(* Logix 5000 project; controller Motion_Axis_AOIs_AMCI_RSLogix_V31 vendor 1 type 14 code 108 rev 31.11; software revision 31.02; part 4 of 7 *)

ADD_ON_INSTRUCTION AMCI_MA_SV_Linear_Follower   (* revision 1.1, vendor AMCI, ExecuteEnableInFalse *)
// Only for SVXXXE2 motion devices.
// Revision note:
// Version 1.1:  Corrected mistake in the text on the Help Tab.
// Help:
// MOTION AXIS SV CIRCULAR FOLLOWER
// These AOIs will only work with the SV motion devices.  The SMD and SD  motion devices have their own follower AOIs.
// AXIS INPUT DATA:  Input data from AMCI motion device.   Uses the AMCI_Motion_Axis_Input_Data User Defined Data Type.
// AXIS OUTPUT DATA; Output data from the AOI to the AMCI motion device.   Uses the AMCI_Motion_Axis_Output_Data User Defined Data Type.
// FOLLOWER POSITION: REAL DATA TYPE position directly from the motion axis.
// FOLLOWER VELOCITY: REAL DATA TYPE velocity directly from the motion axis.
// FOLLOWER ACCELERATION: REAL DATA TYPE acceleration directly from the motion axis.
// RAMP ACCELERATION: An actual value or INT value used to transition from no motion to motion.   Once
//                                          motion is occurring, the follower acceleration will be used.  Range of 0 to 15,999.
// DECELERATION: An actual value or INT value used to transition from motion to no motion.   Range of 0 to
//                              15,999.
// EN (Enable) Set when rung is true, Reset when rung is false
// DN (Done) Set when command is sent to the motion device.  Reset when the rung is false.
// ER (Error) Set when a command or input error failed to clear.  Reset when the rung is false.
// IP (In Process) Set when motion is occurring.   Reset when the rung goes false.
VAR_IN_OUT
   Axis_Input_Data : AMCI_Motion_Axis_Input_Data; {required}
   Axis_Output_Data : AMCI_Motion_Axis_Output_Data; {required}
END_VAR
VAR_INPUT
   Follower_Position : REAL; {required}
   Follower_Velocity : REAL; {required}
   Follower_Acceleration : REAL; {required}
   Ramp_Acceleration : INT; {required}
   Deceleration : INT; {required}
   Maximum_Move_Torque : INT;
END_VAR
VAR_OUTPUT
   EN : BOOL; {visible}
   ER : BOOL; {visible}
   DN : BOOL; {access Read Only, visible}
   IP : BOOL; {access Read Only, visible}
END_VAR
VAR
   command_data_block : INT[10];
        [2]   // Upper Target Position
        [4]   // Upper Programmed Speed
        [1]   // Command Bits LSW
        [3]   // Lower Target Position
        [5]   // Lower Programmed Speed
        [0]   // Command Bits MSW
   axis_follower_position : DINT;
   axis_follower_velocity : DINT;
END_VAR

ROUTINE EnableInFalse   (* ladder *)
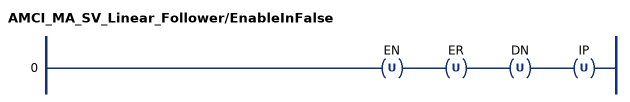
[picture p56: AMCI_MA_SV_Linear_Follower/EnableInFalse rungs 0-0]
   0: OTU(EN)OTU(ER)OTU(DN)OTU(IP);
END_ROUTINE

ROUTINE Logic   (* ladder *)
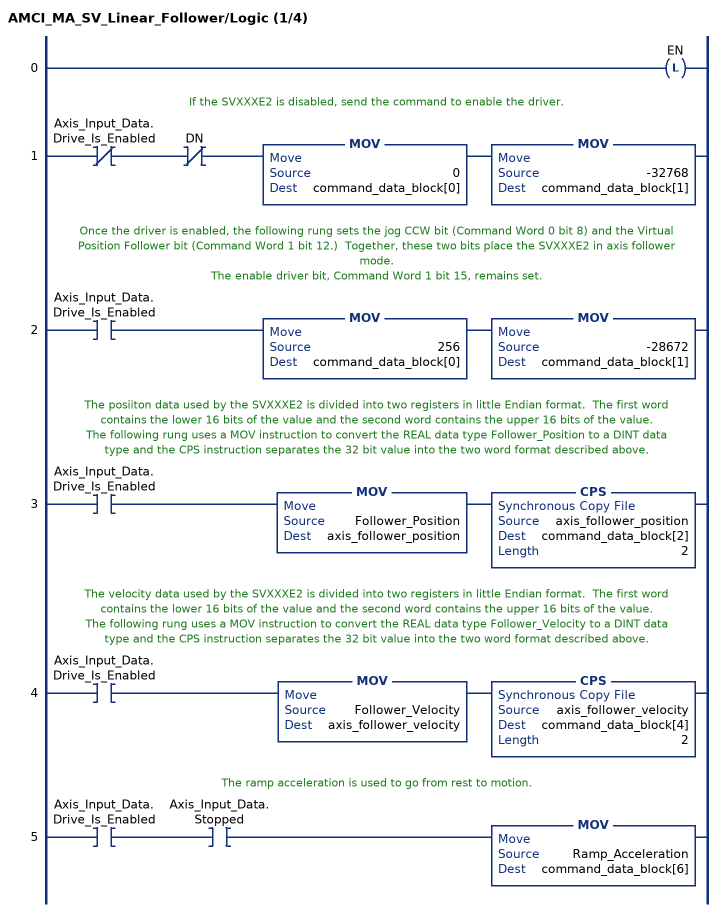
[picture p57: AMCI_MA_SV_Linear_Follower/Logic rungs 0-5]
   0: OTL(EN);
   // If the SVXXXE2 is disabled, send the command to enable the driver.
   1: XIO(Axis_Input_Data.Drive_Is_Enabled)XIO(DN)MOV(0,command_data_block[0])MOV(-32768,command_data_block[1]);
   // Once the driver is enabled, the following rung sets the jog CCW bit (Command Word 0 bit 8) and the Virtual Position Follower bit (Command Word 1 bit 12.)  Together, these two bits place the SVXXXE2 in axis follower mode.
   // The enable driver bit, Command Word 1 bit 15, remains set.
   2: XIC(Axis_Input_Data.Drive_Is_Enabled)MOV(256,command_data_block[0])MOV(-28672,command_data_block[1]);
   // The posiiton data used by the SVXXXE2 is divided into two registers in little Endian format.  The first word contains the lower 16 bits of the value and the second word contains the upper 16 bits of the value.
   // The following rung uses a MOV instruction to convert the REAL data type Follower_Position to a DINT data type and the CPS instruction separates the 32 bit value into the two word format described above.
   3: XIC(Axis_Input_Data.Drive_Is_Enabled)MOV(Follower_Position,axis_follower_position)CPS(axis_follower_position,command_data_block[2],2);
   // The velocity data used by the SVXXXE2 is divided into two registers in little Endian format.  The first word contains the lower 16 bits of the value and the second word contains the upper 16 bits of the value.
   // The following rung uses a MOV instruction to convert the REAL data type Follower_Velocity to a DINT data type and the CPS instruction separates the 32 bit value into the two word format described above.
   4: XIC(Axis_Input_Data.Drive_Is_Enabled)MOV(Follower_Velocity,axis_follower_velocity)CPS(axis_follower_velocity,command_data_block[4],2);
   // The ramp acceleration is used to go from rest to motion.
   5: XIC(Axis_Input_Data.Drive_Is_Enabled)XIC(Axis_Input_Data.Stopped)MOV(Ramp_Acceleration,command_data_block[6]);
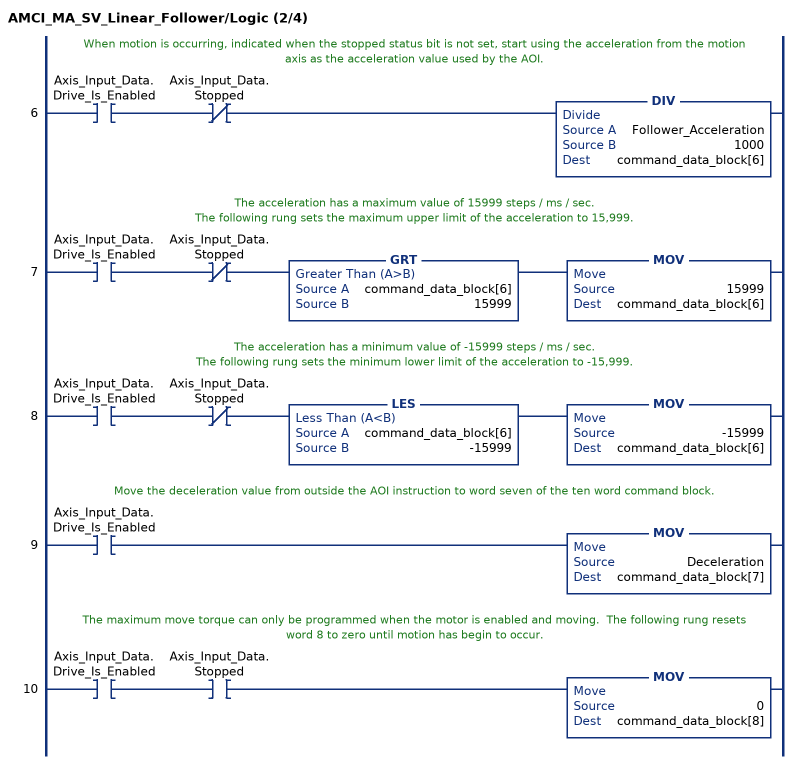
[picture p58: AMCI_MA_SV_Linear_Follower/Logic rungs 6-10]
   // When motion is occurring, indicated when the stopped status bit is not set, start using the acceleration from the motion axis as the acceleration value used by the AOI.
   6: XIC(Axis_Input_Data.Drive_Is_Enabled)XIO(Axis_Input_Data.Stopped)DIV(Follower_Acceleration,1000,command_data_block[6]);
   // The acceleration has a maximum value of 15999 steps / ms / sec.
   // The following rung sets the maximum upper limit of the acceleration to 15,999.
   7: XIC(Axis_Input_Data.Drive_Is_Enabled)XIO(Axis_Input_Data.Stopped)GRT(command_data_block[6],15999)MOV(15999,command_data_block[6]);
   // The acceleration has a minimum value of -15999 steps / ms / sec.
   // The following rung sets the minimum lower limit of the acceleration to -15,999.
   8: XIC(Axis_Input_Data.Drive_Is_Enabled)XIO(Axis_Input_Data.Stopped)LES(command_data_block[6],-15999)MOV(-15999,command_data_block[6]);
   // Move the deceleration value from outside the AOI instruction to word seven of the ten word command block.
   9: XIC(Axis_Input_Data.Drive_Is_Enabled)MOV(Deceleration,command_data_block[7]);
   // The maximum move torque can only be programmed when the motor is enabled and moving.  The following rung resets word 8 to zero until motion has begin to occur.
   10: XIC(Axis_Input_Data.Drive_Is_Enabled)XIC(Axis_Input_Data.Stopped)MOV(0,command_data_block[8]);
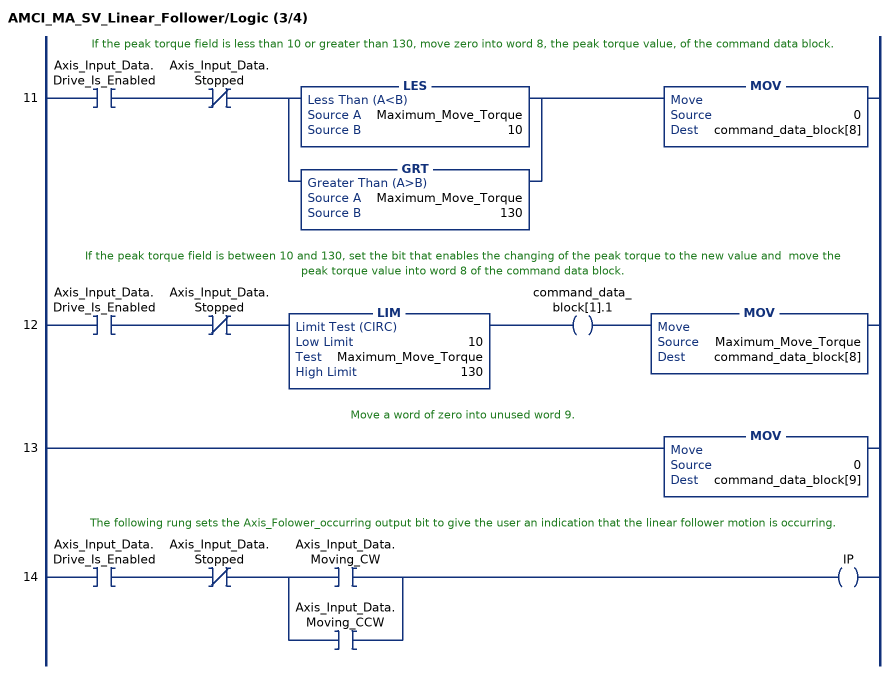
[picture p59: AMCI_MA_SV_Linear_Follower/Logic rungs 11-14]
   // If the peak torque field is less than 10 or greater than 130, move zero into word 8, the peak torque value, of the command data block.
   11: XIC(Axis_Input_Data.Drive_Is_Enabled)XIO(Axis_Input_Data.Stopped)[LES(Maximum_Move_Torque,10) ,GRT(Maximum_Move_Torque,130) ]MOV(0,command_data_block[8]);
   // If the peak torque field is between 10 and 130, set the bit that enables the changing of the peak torque to the new value and  move the peak torque value into word 8 of the command data block.
   12: XIC(Axis_Input_Data.Drive_Is_Enabled)XIO(Axis_Input_Data.Stopped)LIM(10,Maximum_Move_Torque,130)OTE(command_data_block[1].1)MOV(Maximum_Move_Torque,command_data_block[8]);
   // Move a word of zero into unused word 9.
   13: MOV(0,command_data_block[9]);
   // The following rung sets the Axis_Folower_occurring output bit to give the user an indication that the linear follower motion is occurring.
   14: XIC(Axis_Input_Data.Drive_Is_Enabled)XIO(Axis_Input_Data.Stopped)[XIC(Axis_Input_Data.Moving_CW) ,XIC(Axis_Input_Data.Moving_CCW) ]OTE(IP);
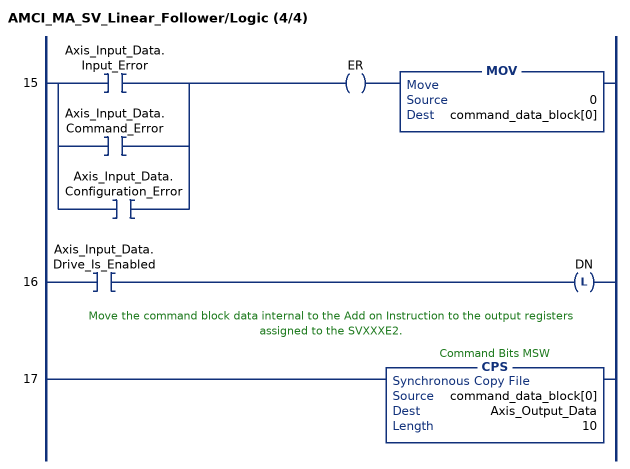
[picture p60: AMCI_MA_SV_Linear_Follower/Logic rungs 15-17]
   15: [XIC(Axis_Input_Data.Input_Error) ,XIC(Axis_Input_Data.Command_Error) ,XIC(Axis_Input_Data.Configuration_Error) ]OTE(ER)MOV(0,command_data_block[0]);
   16: XIC(Axis_Input_Data.Drive_Is_Enabled)OTL(DN);
   // Move the command block data internal to the Add on Instruction to the output registers assigned to the SVXXXE2.
   17: CPS(command_data_block[0],Axis_Output_Data,10);
END_ROUTINE
END_ADD_ON_INSTRUCTION

ADD_ON_INSTRUCTION AMCI_MA_SV_Linear_Follower_CIPSync   (* revision 1.0, vendor AMCI, ExecuteEnableInFalse *)
// Only for SVXXXE2 motion devices.
// Revision note:
// 8/8/24.  Added CIPSync functionality to a previously existing AOI.  The abiltiy to change the maximum move torque is no longer available because the time value uses the same output words as the torque value.
// Help:
// MOTION AXIS SV CIRCULAR FOLLOWER
// These AOIs will only work with the SD and SMD motion devices.  The SV motion devices have their own follower AOIs.
// AXIS INPUT DATA:  Input data from AMCI motion device.   Uses the AMCI_Motion_Axis_Input_Data User Defined Data Type.
// AXIS OUTPUT DATA; Output data from the AOI to the AMCI motion device.   Uses the AMCI_Motion_Axis_Output_Data User Defined Data Type.
// FOLLOWER POSITION: REAL DATA TYPE position directly from the motion axis.
// FOLLOWER VELOCITY: REAL DATA TYPE velocity directly from the motion axis.
// FOLLOWER ACCELERATION: REAL DATA TYPE acceleration directly from the motion axis.
// RAMP ACCELERATION: An actual value or INT value used to transition from no motion to motion.   Once
//                                          motion is occurring, the follower acceleration will be used.  Range of 0 to 15,999.
// DECELERATION: An actual value or INT value used to transition from motion to no motion.   Range of 0 to
//                              15,999.
// EN (Enable) Set when rung is true, Reset when rung is false
// DN (Done) Set when command is sent to the motion device.  Reset when the rung is false.
// ER (Error) Set when a command or input error failed to clear.  Reset when the rung is false.
// IP (In Process) Set when motion is occurring.   Reset when the rung goes false.
VAR_IN_OUT
   Axis_Input_Data : AMCI_Motion_Axis_Input_Data; {required}
   Axis_Output_Data : AMCI_Motion_Axis_Output_Data; {required}
END_VAR
VAR_INPUT
   current_system_time : DINT; {required}
   Follower_Position : REAL; {required}
   Follower_Velocity : REAL; {required}
   Follower_Acceleration : REAL; {required}
   Ramp_Acceleration : INT; {required}
   Deceleration : INT; {required}
END_VAR
VAR_OUTPUT
   EN : BOOL; {visible}
   ER : BOOL; {visible}
   DN : BOOL; {access Read Only, visible}
   IP : BOOL; {access Read Only, visible}
END_VAR
VAR
   command_data_block : INT[10];
        [2]   // Upper Target Position
        [4]   // Upper Programmed Speed
        [5]   // Lower Programmed Speed
        [0]   // Command Bits MSW
        [1]   // Command Bits LSW
        [3]   // Lower Target Position
   axis_follower_position : DINT;
   axis_follower_velocity : DINT;
END_VAR

ROUTINE EnableInFalse   (* ladder *)
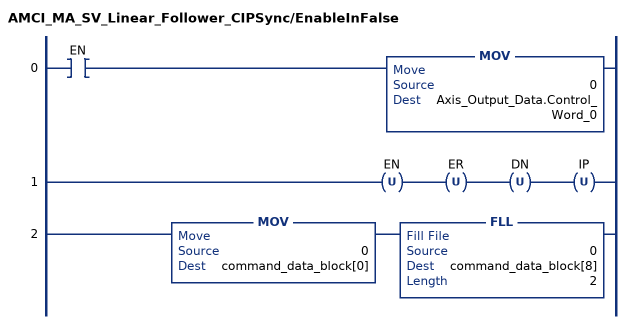
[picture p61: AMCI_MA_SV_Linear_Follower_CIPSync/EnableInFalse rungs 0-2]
   0: XIC(EN)MOV(0,Axis_Output_Data.Control_Word_0);
   1: OTU(EN)OTU(ER)OTU(DN)OTU(IP);
   2: MOV(0,command_data_block[0])FLL(0,command_data_block[8],2);
END_ROUTINE

ROUTINE Logic   (* ladder *)
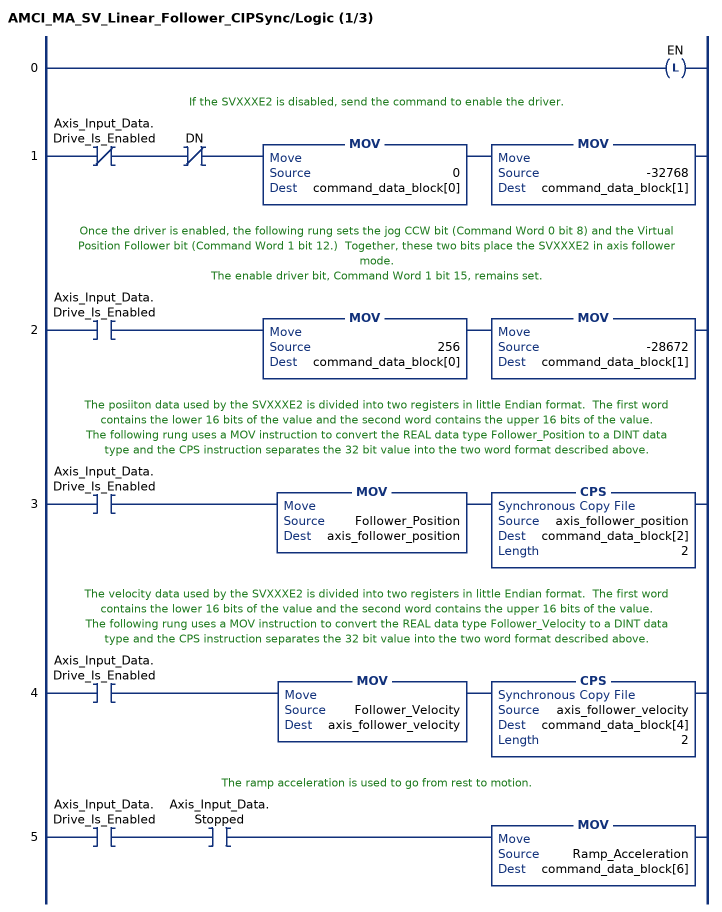
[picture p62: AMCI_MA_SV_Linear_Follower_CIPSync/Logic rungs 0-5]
   0: OTL(EN);
   // If the SVXXXE2 is disabled, send the command to enable the driver.
   1: XIO(Axis_Input_Data.Drive_Is_Enabled)XIO(DN)MOV(0,command_data_block[0])MOV(-32768,command_data_block[1]);
   // Once the driver is enabled, the following rung sets the jog CCW bit (Command Word 0 bit 8) and the Virtual Position Follower bit (Command Word 1 bit 12.)  Together, these two bits place the SVXXXE2 in axis follower mode.
   // The enable driver bit, Command Word 1 bit 15, remains set.
   2: XIC(Axis_Input_Data.Drive_Is_Enabled)MOV(256,command_data_block[0])MOV(-28672,command_data_block[1]);
   // The posiiton data used by the SVXXXE2 is divided into two registers in little Endian format.  The first word contains the lower 16 bits of the value and the second word contains the upper 16 bits of the value.
   // The following rung uses a MOV instruction to convert the REAL data type Follower_Position to a DINT data type and the CPS instruction separates the 32 bit value into the two word format described above.
   3: XIC(Axis_Input_Data.Drive_Is_Enabled)MOV(Follower_Position,axis_follower_position)CPS(axis_follower_position,command_data_block[2],2);
   // The velocity data used by the SVXXXE2 is divided into two registers in little Endian format.  The first word contains the lower 16 bits of the value and the second word contains the upper 16 bits of the value.
   // The following rung uses a MOV instruction to convert the REAL data type Follower_Velocity to a DINT data type and the CPS instruction separates the 32 bit value into the two word format described above.
   4: XIC(Axis_Input_Data.Drive_Is_Enabled)MOV(Follower_Velocity,axis_follower_velocity)CPS(axis_follower_velocity,command_data_block[4],2);
   // The ramp acceleration is used to go from rest to motion.
   5: XIC(Axis_Input_Data.Drive_Is_Enabled)XIC(Axis_Input_Data.Stopped)MOV(Ramp_Acceleration,command_data_block[6]);
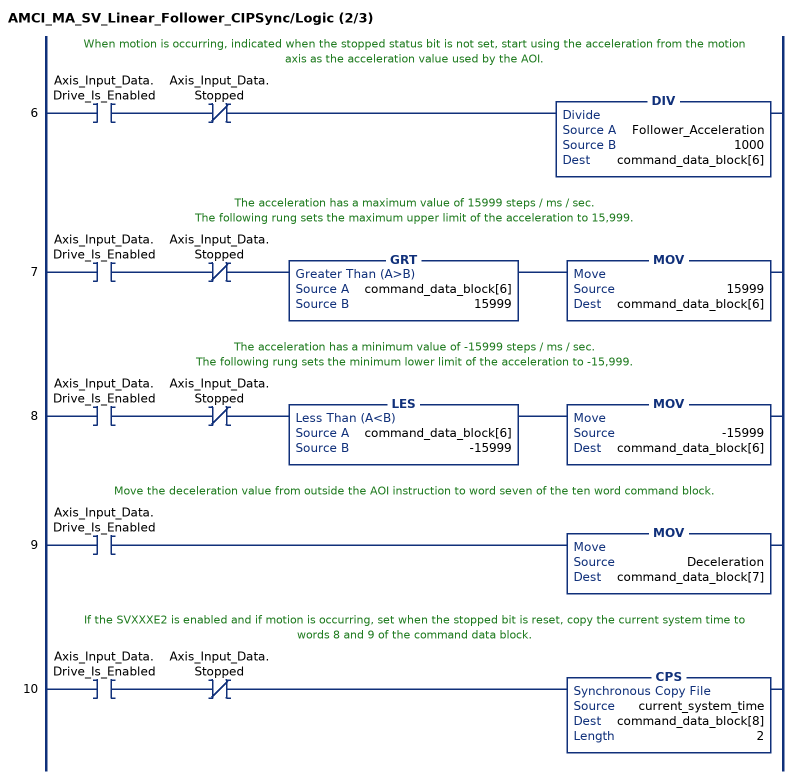
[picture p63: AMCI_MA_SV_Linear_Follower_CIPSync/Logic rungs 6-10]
   // When motion is occurring, indicated when the stopped status bit is not set, start using the acceleration from the motion axis as the acceleration value used by the AOI.
   6: XIC(Axis_Input_Data.Drive_Is_Enabled)XIO(Axis_Input_Data.Stopped)DIV(Follower_Acceleration,1000,command_data_block[6]);
   // The acceleration has a maximum value of 15999 steps / ms / sec.
   // The following rung sets the maximum upper limit of the acceleration to 15,999.
   7: XIC(Axis_Input_Data.Drive_Is_Enabled)XIO(Axis_Input_Data.Stopped)GRT(command_data_block[6],15999)MOV(15999,command_data_block[6]);
   // The acceleration has a minimum value of -15999 steps / ms / sec.
   // The following rung sets the minimum lower limit of the acceleration to -15,999.
   8: XIC(Axis_Input_Data.Drive_Is_Enabled)XIO(Axis_Input_Data.Stopped)LES(command_data_block[6],-15999)MOV(-15999,command_data_block[6]);
   // Move the deceleration value from outside the AOI instruction to word seven of the ten word command block.
   9: XIC(Axis_Input_Data.Drive_Is_Enabled)MOV(Deceleration,command_data_block[7]);
   // If the SVXXXE2 is enabled and if motion is occurring, set when the stopped bit is reset, copy the current system time to words 8 and 9 of the command data block.
   10: XIC(Axis_Input_Data.Drive_Is_Enabled)XIO(Axis_Input_Data.Stopped)CPS(current_system_time,command_data_block[8],2);
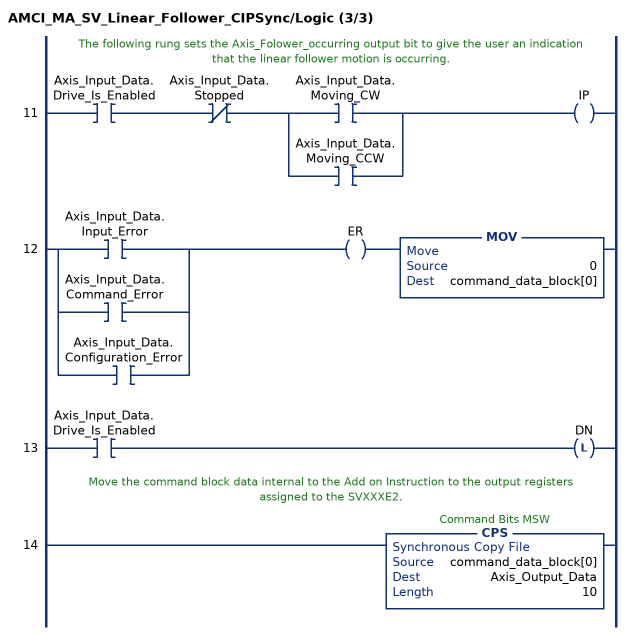
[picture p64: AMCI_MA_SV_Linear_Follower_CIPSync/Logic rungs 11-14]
   // The following rung sets the Axis_Folower_occurring output bit to give the user an indication that the linear follower motion is occurring.
   11: XIC(Axis_Input_Data.Drive_Is_Enabled)XIO(Axis_Input_Data.Stopped)[XIC(Axis_Input_Data.Moving_CW) ,XIC(Axis_Input_Data.Moving_CCW) ]OTE(IP);
   12: [XIC(Axis_Input_Data.Input_Error) ,XIC(Axis_Input_Data.Command_Error) ,XIC(Axis_Input_Data.Configuration_Error) ]OTE(ER)MOV(0,command_data_block[0]);
   13: XIC(Axis_Input_Data.Drive_Is_Enabled)OTL(DN);
   // Move the command block data internal to the Add on Instruction to the output registers assigned to the SVXXXE2.
   14: CPS(command_data_block[0],Axis_Output_Data,10);
END_ROUTINE
END_ADD_ON_INSTRUCTION

ADD_ON_INSTRUCTION AMCI_MAFR   (* revision 1.1, vendor AMCI, ExecuteEnableInFalse *)
// AMCI Reset Errors
// Revision note:
// V1.1 11/17/23 Reset output word 0 to 0 when the rung goes false.
// Help:
// MOTION AXIS FAULT RESET:   Resets Command, Input, and Stall Detect Errors.  It will also reset the Move Complete Status Bit.
// Note: This instruction will maintain the motion device’s current enabled state.  That is, if the device is enabled,
//            it will remain enabled.  If it is disabled, it will remain disabled.
// AXIS INPUT DATA:  Input data from AMCI motion device.   Uses the AMCI_Motion_Axis_Input_Data User Defined Data Type.
// AXIS OUTPUT DATA; Output data from the AOI to the AMCI motion device.   Uses the AMCI_Motion_Axis_Output_Data User Defined Data Type.
// EN (Enable) Set when rung is true, Reset when rung is false
// DN (Done) Set when command is sent to the motion device.  Reset when the rung is false.
// ER (Error) Set when a command or input error failed to clear.  Reset when the rung is false.
VAR_IN_OUT
   Axis_Input_Data : AMCI_Motion_Axis_Input_Data; {required}
   Axis_Output_Data : AMCI_Motion_Axis_Output_Data; {required}
END_VAR
VAR_OUTPUT
   EN : BOOL; {visible}   // set when rung with AOI is true
   DN : BOOL; {access Read Only, visible}   // set when reset error command sent to motion axis
   ER : BOOL; {access Read Only, visible}   // set when reset error command did not clear the error
END_VAR
VAR
   command_data_block : INT[10];
        [3]   // Lower Target Position
        [5]   // Lower Programmed Speed
        [1]   // Command Bits LSW
        [0]   // Command Bits MSW
        [2]   // Upper Target Position
        [4]   // Upper Programmed Speed
END_VAR

ROUTINE EnableInFalse   (* ladder *)
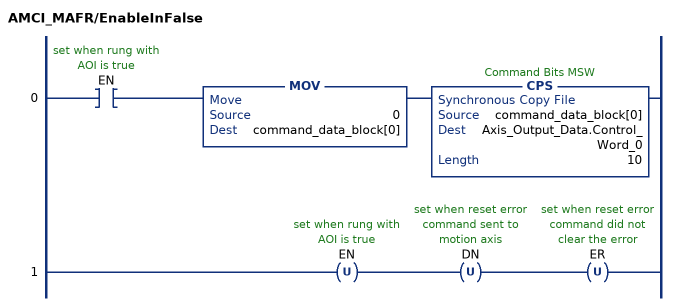
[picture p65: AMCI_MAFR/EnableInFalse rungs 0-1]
   0: XIC(EN)MOV(0,command_data_block[0])CPS(command_data_block[0],Axis_Output_Data.Control_Word_0,10);
   1: OTU(EN)OTU(DN)OTU(ER);
END_ROUTINE

ROUTINE Logic   (* ladder *)
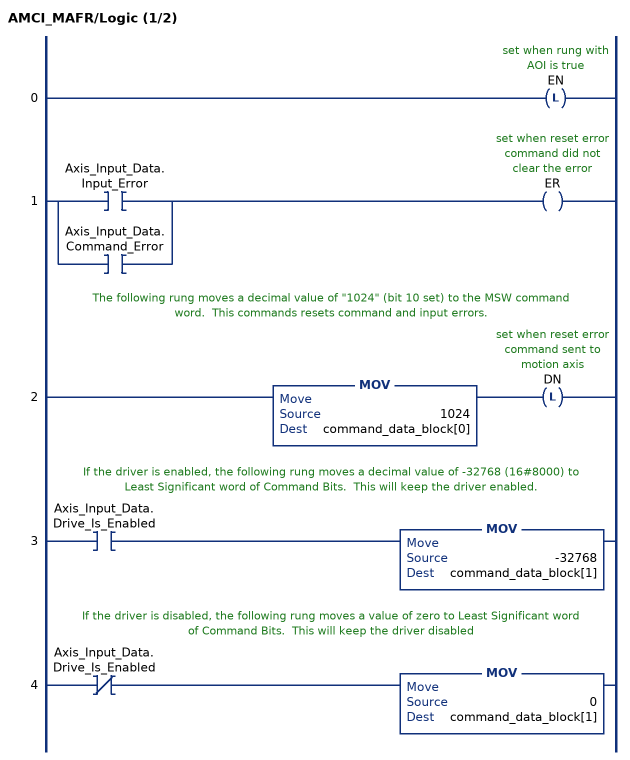
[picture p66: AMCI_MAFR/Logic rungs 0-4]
   0: OTL(EN);
   1: [XIC(Axis_Input_Data.Input_Error) ,XIC(Axis_Input_Data.Command_Error) ]OTE(ER);
   // The following rung moves a decimal value of "1024" (bit 10 set) to the MSW command word.  This commands resets command and input errors.
   2: MOV(1024,command_data_block[0])OTL(DN);
   // If the driver is enabled, the following rung moves a decimal value of -32768 (16#8000) to Least Significant word of Command Bits.  This will keep the driver enabled.
   3: XIC(Axis_Input_Data.Drive_Is_Enabled)MOV(-32768,command_data_block[1]);
   // If the driver is disabled, the following rung moves a value of zero to Least Significant word of Command Bits.  This will keep the driver disabled
   4: XIO(Axis_Input_Data.Drive_Is_Enabled)MOV(0,command_data_block[1]);
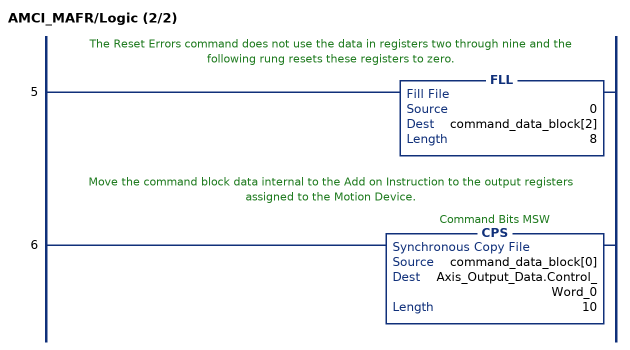
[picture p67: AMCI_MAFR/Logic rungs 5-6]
   // The Reset Errors command does not use the data in registers two through nine and the following rung resets these registers to zero.
   5: FLL(0,command_data_block[2],8);
   // Move the command block data internal to the Add on Instruction to the output registers assigned to the Motion Device.
   6: CPS(command_data_block[0],Axis_Output_Data.Control_Word_0,10);
END_ROUTINE
END_ADD_ON_INSTRUCTION

ADD_ON_INSTRUCTION AMCI_MAH   (* revision 1.0, vendor AMCI, ExecuteEnableInFalse *)
// AMCI Motion Axis Home
// Revision note:
// 11/28/22 Initial release of AOI
// Help:
// MOTION AXIS HOME:   Performs CW or CCW Home Moves to a Home Input.
// AXIS INPUT DATA:  Input data from AMCI motion device.   Uses the AMCI_Motion_Axis_Input_Data User Defined Data Type.
// AXIS OUTPUT DATA; Output data from the AOI to the AMCI motion device.   Uses the AMCI_Motion_Axis_Output_Data User Defined Data Type.
// DIRECTION: 0 = CW Home, 1 = CCW Home
// PROGRAMMED SPEED: Speed of move in units of steps / sec
// ACCELERATION: Acceleration Rate in units of steps / sec / ms
// DECELERATION:  Deceleration Rate in units of steps / sec / ms
// EN (Enable) Set when rung is true, Reset when rung is false
// DN (Done) Set when command is sent to the motion device.  Reset when the rung is false.
// ER (Error) Set when a command or input error failed to clear.  Reset when the rung is false.
// IP (In Process) Set when motion is occurring.   Reset when motion stops or the rung goes false.
// PC (Process Complete) Set when the At Home Status bit is set.   Reset the next time the rung with the AOI                                      goes from false to true.
VAR_IN_OUT
   Axis_Input_Data : AMCI_Motion_Axis_Input_Data; {required}
   Axis_Output_Data : AMCI_Motion_Axis_Output_Data; {required}
END_VAR
VAR_INPUT
   Direction_0_CW_1_CCW : BOOL; {required}   // 0=home CW 1=home CCW
   Programmed_Speed : DINT; {required}
   Acceleration : INT; {required}
   Deceleration : INT; {required}
END_VAR
VAR_OUTPUT
   EN : BOOL; {visible}   // set when rung with AOI is true
   DN : BOOL; {access Read Only, visible}   // set when move was succesfully initiated
   ER : BOOL; {visible}   // input, command, or configuration error
   IP : BOOL; {visible}   // set when motion occurring
   PC : BOOL; {visible}   // set when process complete
END_VAR
VAR
   command_data_block : INT[10];
        [5]   // Lower Programmed Speed
        [0]   // Command Bits MSW
        [2]   // Upper Target Position
        [4]   // Upper Programmed Speed
        [1]   // Command Bits LSW
        [3]   // Lower Target Position
   motion_occurring : BOOL; {access None}
   Internal_Enable : BOOL; {access None}   // set when driver ready to receive motion command
END_VAR

ROUTINE EnableInFalse   (* ladder *)
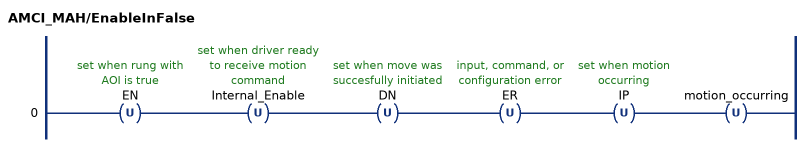
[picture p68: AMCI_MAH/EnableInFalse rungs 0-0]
   0: OTU(EN)OTU(Internal_Enable)OTU(DN)OTU(ER)OTU(IP)OTU(motion_occurring);
END_ROUTINE

ROUTINE Logic   (* ladder *)
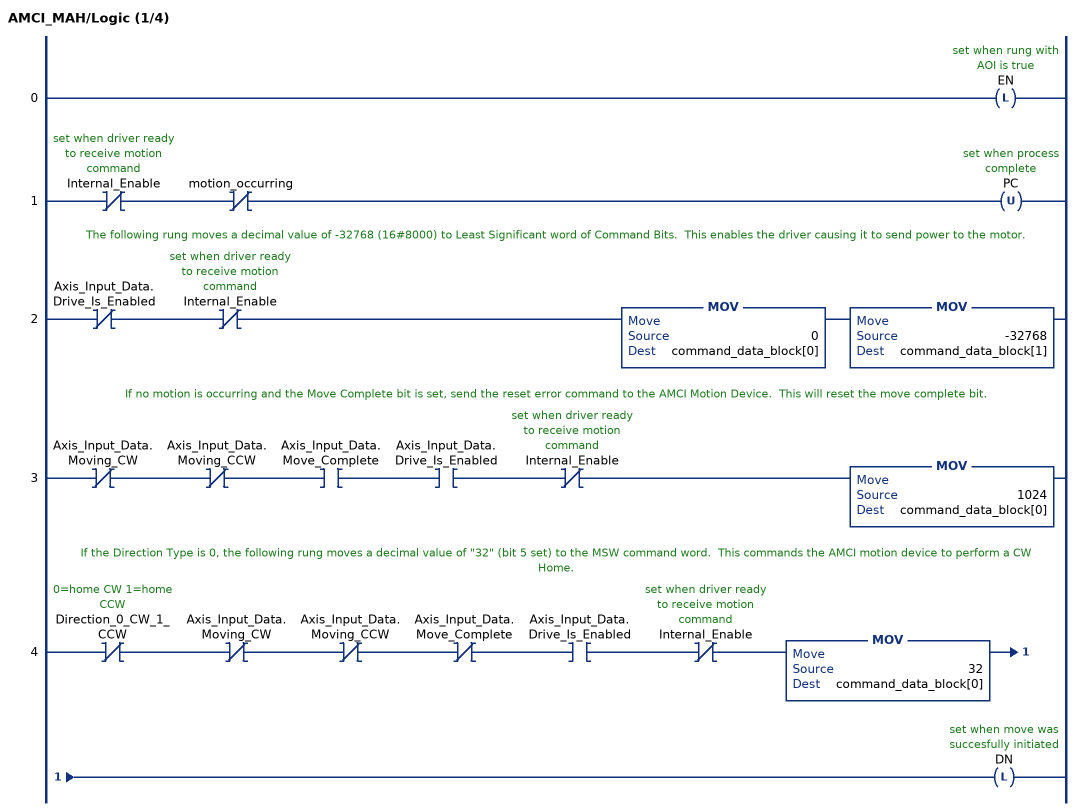
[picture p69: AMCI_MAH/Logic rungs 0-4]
   0: OTL(EN);
   1: XIO(Internal_Enable)XIO(motion_occurring)OTU(PC);
   // The following rung moves a decimal value of -32768 (16#8000) to Least Significant word of Command Bits.  This enables the driver causing it to send power to the motor.
   2: XIO(Axis_Input_Data.Drive_Is_Enabled)XIO(Internal_Enable)MOV(0,command_data_block[0])MOV(-32768,command_data_block[1]);
   // If no motion is occurring and the Move Complete bit is set, send the reset error command to the AMCI Motion Device.  This will reset the move complete bit.
   3: XIO(Axis_Input_Data.Moving_CW)XIO(Axis_Input_Data.Moving_CCW)XIC(Axis_Input_Data.Move_Complete)XIC(Axis_Input_Data.Drive_Is_Enabled)XIO(Internal_Enable)MOV(1024,command_data_block[0]);
   // If the Direction Type is 0, the following rung moves a decimal value of "32" (bit 5 set) to the MSW command word.  This commands the AMCI motion device to perform a CW Home.
   4: XIO(Direction_0_CW_1_CCW)XIO(Axis_Input_Data.Moving_CW)XIO(Axis_Input_Data.Moving_CCW)XIO(Axis_Input_Data.Move_Complete)XIC(Axis_Input_Data.Drive_Is_Enabled)XIO(Internal_Enable)MOV(32,command_data_block[0])OTL(DN);
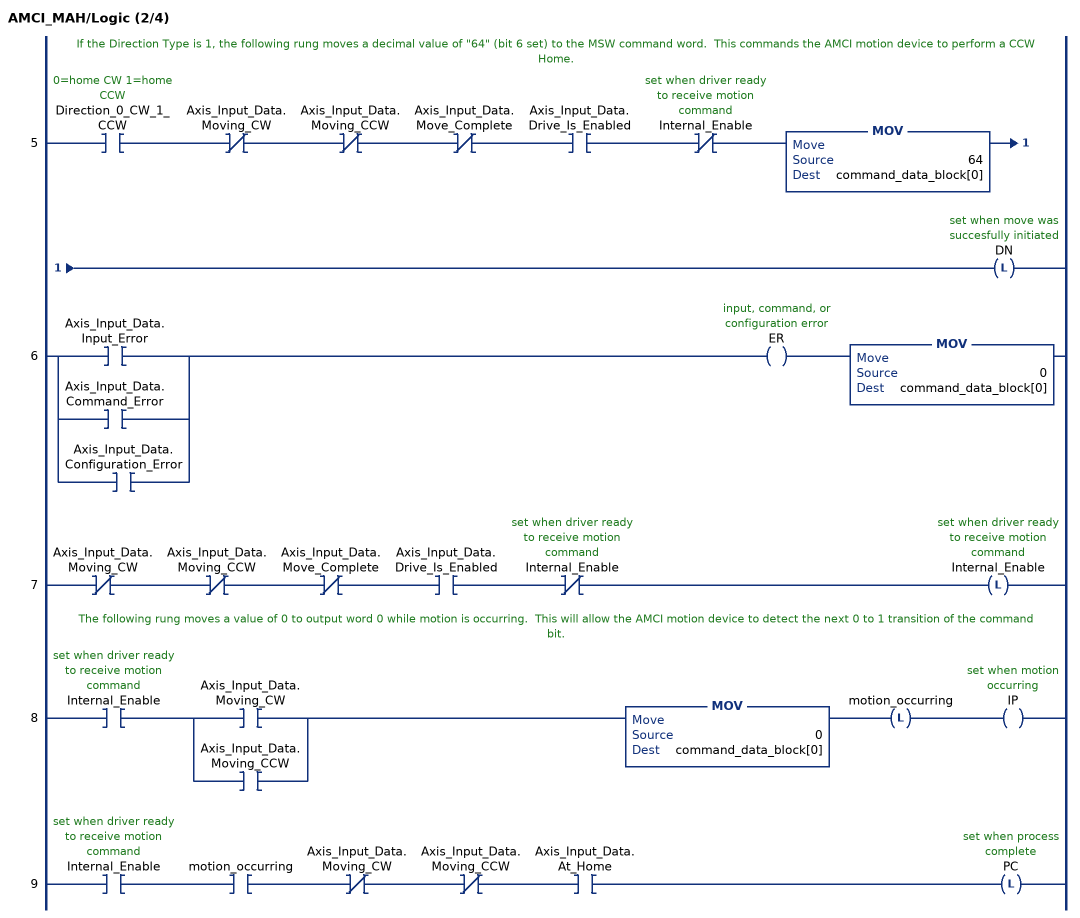
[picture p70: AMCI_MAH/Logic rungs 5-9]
   // If the Direction Type is 1, the following rung moves a decimal value of "64" (bit 6 set) to the MSW command word.  This commands the AMCI motion device to perform a CCW Home.
   5: XIC(Direction_0_CW_1_CCW)XIO(Axis_Input_Data.Moving_CW)XIO(Axis_Input_Data.Moving_CCW)XIO(Axis_Input_Data.Move_Complete)XIC(Axis_Input_Data.Drive_Is_Enabled)XIO(Internal_Enable)MOV(64,command_data_block[0])OTL(DN);
   6: [XIC(Axis_Input_Data.Input_Error) ,XIC(Axis_Input_Data.Command_Error) ,XIC(Axis_Input_Data.Configuration_Error) ]OTE(ER)MOV(0,command_data_block[0]);
   7: XIO(Axis_Input_Data.Moving_CW)XIO(Axis_Input_Data.Moving_CCW)XIO(Axis_Input_Data.Move_Complete)XIC(Axis_Input_Data.Drive_Is_Enabled)XIO(Internal_Enable)OTL(Internal_Enable);
   // The following rung moves a value of 0 to output word 0 while motion is occurring.  This will allow the AMCI motion device to detect the next 0 to 1 transition of the command bit.
   8: XIC(Internal_Enable)[XIC(Axis_Input_Data.Moving_CW) ,XIC(Axis_Input_Data.Moving_CCW) ]MOV(0,command_data_block[0])OTL(motion_occurring)OTE(IP);
   9: XIC(Internal_Enable)XIC(motion_occurring)XIO(Axis_Input_Data.Moving_CW)XIO(Axis_Input_Data.Moving_CCW)XIC(Axis_Input_Data.At_Home)OTL(PC);
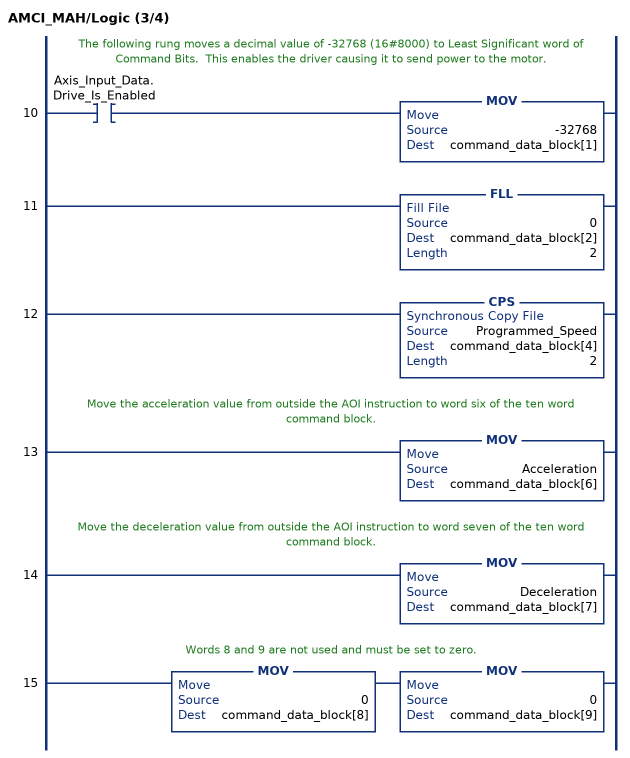
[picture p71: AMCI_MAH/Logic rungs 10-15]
   // The following rung moves a decimal value of -32768 (16#8000) to Least Significant word of Command Bits.  This enables the driver causing it to send power to the motor.
   10: XIC(Axis_Input_Data.Drive_Is_Enabled)MOV(-32768,command_data_block[1]);
   11: FLL(0,command_data_block[2],2);
   12: CPS(Programmed_Speed,command_data_block[4],2);
   // Move the acceleration value from outside the AOI instruction to word six of the ten word command block.
   13: MOV(Acceleration,command_data_block[6]);
   // Move the deceleration value from outside the AOI instruction to word seven of the ten word command block.
   14: MOV(Deceleration,command_data_block[7]);
   // Words 8 and 9 are not used and must be set to zero.
   15: MOV(0,command_data_block[8])MOV(0,command_data_block[9]);
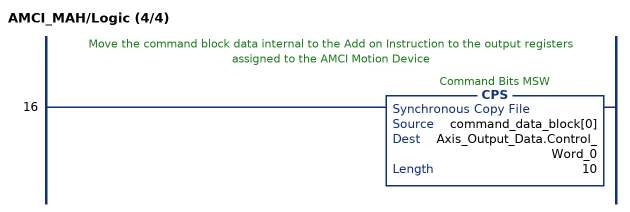
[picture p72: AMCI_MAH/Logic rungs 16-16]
   // Move the command block data internal to the Add on Instruction to the output registers assigned to the AMCI Motion Device
   16: CPS(command_data_block[0],Axis_Output_Data.Control_Word_0,10);
END_ROUTINE
END_ADD_ON_INSTRUCTION

ADD_ON_INSTRUCTION AMCI_MAJ   (* revision 1.0, vendor AMCI, ExecuteEnableInFalse *)
// AMCI Motion Axis Jog
// Revision note:
// 11/23/22 Initial release of AOI
// Help:
// MOTION AXIS JOG: Performs CW or CCW Jog Moves
// AXIS INPUT DATA:  Input data from AMCI motion device.   Uses the AMCI_Motion_Axis_Input_Data User Defined Data Type.
// AXIS OUTPUT DATA; Output data from the AOI to the AMCI motion device.   Uses the AMCI_Motion_Axis_Output_Data User Defined Data Type.
// DIRECTION: 0 = CW Jog 1 = CCW Jog
// PROGRAMMED SPEED: Speed of move in units of steps / sec
// ACCELERATION: Acceleration Rate in units of steps / sec / ms
// DECELERATION:  Deceleration Rate in units of steps / sec / ms
// EN (Enable) Set when rung is true, Reset when rung is false
// DN (Done) Set when command is sent to the motion device.  Reset when the rung is false.
// ER (Error) Set when a command or input error failed to clear.  Reset when the rung is false.
// IP (In Process) Set when motion is occurring.   Reset when motion stops or the rung goes false.
VAR_IN_OUT
   Axis_Input_Data : AMCI_Motion_Axis_Input_Data; {required}
   Axis_Output_Data : AMCI_Motion_Axis_Output_Data; {required}
END_VAR
VAR_INPUT
   Direction_0_CW_1_CCW : BOOL; {required}   // 0=jog CW 1=jog CCW
   Programmed_Speed : DINT; {required}
   Acceleration : INT; {required}
   Deceleration : INT; {required}
END_VAR
VAR_OUTPUT
   EN : BOOL; {visible}   // set when rung with AOI is true
   DN : BOOL; {access Read Only, visible}   // set when move was succesfully initiated
   ER : BOOL; {visible}
   IP : BOOL; {visible}   // set when motion occurring
END_VAR
VAR
   command_data_block : INT[10];
        [1]   // Command Bits LSW
        [3]   // Lower Target Position
        [5]   // Lower Programmed Speed
        [0]   // Command Bits MSW
        [2]   // Upper Target Position
        [4]   // Upper Programmed Speed
   motion_occurring : BOOL; {access None}
   Internal_Enable : BOOL; {access None}   // set when driver ready to receive motion command
END_VAR

ROUTINE EnableInFalse   (* ladder *)
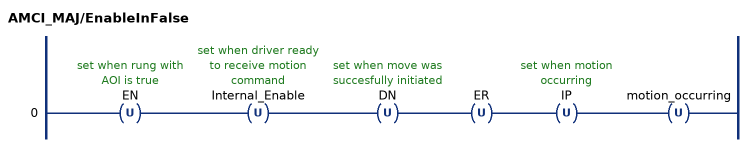
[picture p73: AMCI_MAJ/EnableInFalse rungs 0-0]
   0: OTU(EN)OTU(Internal_Enable)OTU(DN)OTU(ER)OTU(IP)OTU(motion_occurring);
END_ROUTINE
